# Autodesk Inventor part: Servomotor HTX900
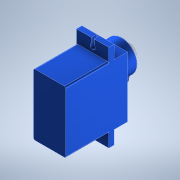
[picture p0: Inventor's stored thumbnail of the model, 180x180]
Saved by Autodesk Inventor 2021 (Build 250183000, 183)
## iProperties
Created: 2016-01
Part Number: Servomotor HTX900
Material: Поликарбонат, дымчатый
Document SubType Name: Modeling
Designer: Evgeny
Density: 1.2 g/cm^3
Appearance: Анодированный — синий
Author: Evgeny
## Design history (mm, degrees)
sketch "Эскиз1"
  geometry: L1 (5.5, 11.5)-(-5.5, 11.5); L2 (-6, 11)-(-6, -11); L3 (-5.5, -11.5)-(5.5, -11.5); L4 (6, -11)-(6, 11); L5 (6, 11.5)-(-6, -11.5); L6 (-6, 11.5)-(6, -11.5); A1 r 0.5 centre (5.5, 11) between (6, 11) and (5.5, 11.5); A2 r 0.5 centre (5.5, -11) between (5.5, -11.5) and (6, -11); A3 r 0.5 centre (-5.5, -11) between (-6, -11) and (-5.5, -11.5); A4 r 0.5 centre (-5.5, 11) between (-5.5, 11.5) and (-6, 11); 1 further point
  constraints: 12 end point, 8 point on circle, 8 point on line, 8 tangent, 4 centre point, 3 equal radius, 2 midpoint, 2 parallel, 1 horizontal, 1 perpendicular
  dimensions: "d0" = 12 distance of L6.end L5.end; "d1" = 23 distance of L5.end L6.start; "d2" = 0.5 radius of A1
extrude "Выдавливание1" new body sketch "Эскиз1" distance "d3" = 16; taper "d4" = 0 deg
sketch "Эскиз2"
  geometry: L1 (6, -16.25)-(6, 16.25); L2 (-6, 16.25)-(-6, -16.25); L3 (-6, -16.25)-(6, 16.25); L4 (6, -16.25)-(-6, 16.25); L5 (-0.5, -14.366)-(-0.5, -16.25); L6 (0.5, -14.366)-(0.5, -16.25); L7 (-6, -16.25)-(-0.5, -16.25); L8 (0.5, -16.25)-(6, -16.25); L9 (-0.5, 14.366)-(-0.5, 16.25); L10 (0.5, 14.366)-(0.5, 16.25); L11 (6, 16.25)-(0.5, 16.25); L12 (-0.5, 16.25)-(-6, 16.25); A1 r 1 centre (0, -13.5) between (0.5, -14.366) and (-0.5, -14.366); A2 r 1 centre (0, 13.5) between (-0.5, 14.366) and (0.5, 14.366); 3 further points
  constraints: 24 end point, 10 perpendicular, 5 parallel, 4 midpoint, 4 point on circle, 2 centre point, 2 collinear, 2 horizontal, 1 vertical alignment
  dimensions: "d5" = 12 distance of L2.start L1.end; "d6" = 32.5 distance of L1.end L1.start; "d7" = 2 diameter of A1; "d8" = 2 diameter of A2 (= d7); "d9" = 1 distance between parallel lines of L6 L5; "d10" = 0.5 distance from line of L5 A1.centre; "d13" = 27 distance of A2.centre A1.centre; "d14" = 13.5 distance of point (0, 0) A1.centre (= 0.5 x d13)
extrude "Выдавливание2" join sketch "Эскиз2" distance "d11" = 2; taper "d12" = 0 deg
sketch "Эскиз3"
  geometry: L1 (6, -16.25)-(6, 16.25) reference; L2 (-6, -11.25)-(6, -11.25); L3 (6, -11.25)-(6, 11.25); L4 (6, 11.25)-(-6, 11.25); L5 (-6, 11.25)-(-6, -11.25); L6 (-6, -11.25)-(6, 11.25); L7 (6, -11.25)-(-6, 11.25); 1 further point
  constraints: 12 end point, 2 midpoint, 2 parallel, 1 horizontal, 1 perpendicular, 1 point on line
  dimensions: "d15" = 22.5 distance of L3.end L2.end; "d18" = 12 distance of L3.end L4.end (derived)
extrude "Выдавливание3" join sketch "Эскиз3" distance "d16" = 5; taper "d17" = 0 deg
sketch "Эскиз4"
  geometry: L1 (-2.75, 0.75)-(-2.75, -0.2); L2 (2.75, 0.75)-(2.75, -0.2); L3 (-6, -11.25)-(6, -11.25) reference; A1 r 5.75 centre (0, -5.25) between (-2.75, -0.2) and (2.75, -0.2); A2 r 2.75 centre (0, 0.75) between (2.75, 0.75) and (-2.75, 0.75); 1 further point
  constraints: 4 end point, 4 point on circle, 2 centre point, 2 tangent, 2 vertical, 2 vertical alignment
  dimensions: "d19" = 11.5 diameter of A1; "d20" = 5.25 distance of A1.centre point (0, 0); "d21" = 5.5 diameter of A2; "d22" = 6 distance of A2.centre A1.centre; "d23" = 11.25 distance from line of point (0, 0) L3 (derived)
extrude "Выдавливание4" join sketch "Эскиз4" distance "d24" = 4; taper "d25" = 0 deg
fillet "Сопряжение1" dims "d26" = 0.25
sketch "Эскиз5"
  geometry: L1 (-4.25, 4.75)-(4.25, 4.75); L2 (4.5, 5)-(4.5, 9.5); L3 (4.25, 9.75)-(-4.25, 9.75); L4 (-4.5, 9.5)-(-4.5, 5); L5 (6, 11.25)-(-6, 11.25) reference; L6 (-6, 11.25)-(-6, -11.25) reference; L7 (6, -11.25)-(6, 11.25) reference; A1 r 0.25 centre (-4.25, 5) between (-4.5, 5) and (-4.25, 4.75); A2 r 0.25 centre (-4.25, 9.5) between (-4.25, 9.75) and (-4.5, 9.5); A3 r 0.25 centre (4.25, 9.5) between (4.5, 9.5) and (4.25, 9.75); A4 r 0.25 centre (4.25, 5) between (4.25, 4.75) and (4.5, 5); 1 further point
  constraints: 8 end point, 8 point on circle, 8 tangent, 4 centre point, 3 equal radius, 2 parallel, 1 horizontal, 1 perpendicular
  dimensions: "d27" = 1.5 distance between parallel lines of L3 L5; "d28" = 1.5 distance between parallel lines of L4 L6 (= d27); "d29" = 1.5 distance between parallel lines of L7 L2 (= d27); "d30" = 5 distance between parallel lines of L1 L3; "d31" = 0.25 radius of A1
extrude "Выдавливание5" cut sketch "Эскиз5" distance "d32" = 0.25; taper "d33" = 0 deg
sketch "Эскиз6"
  geometry: C1 r 2.25 at (0, -5.25); C2 r 0.5 at (0, -5.25); A1 r 5.5 centre (0, -5.25) between (-2.5, -0.351) and (2.5, -0.351) reference; 1 further point
  constraints: 2 centre point, 2 coincident
  dimensions: "d34" = 4.5 diameter of C1; "d35" = 1 diameter of C2
extrude "Выдавливание6" join sketch "Эскиз6" distance "d36" = 3; taper "d37" = 0 deg
node "Твердое тело1"
other parameters: "d39" = 1, "d44" = 0.8, "d45" = 0.4 (= 0.5 x d44), "d93" = 3 (derived)
